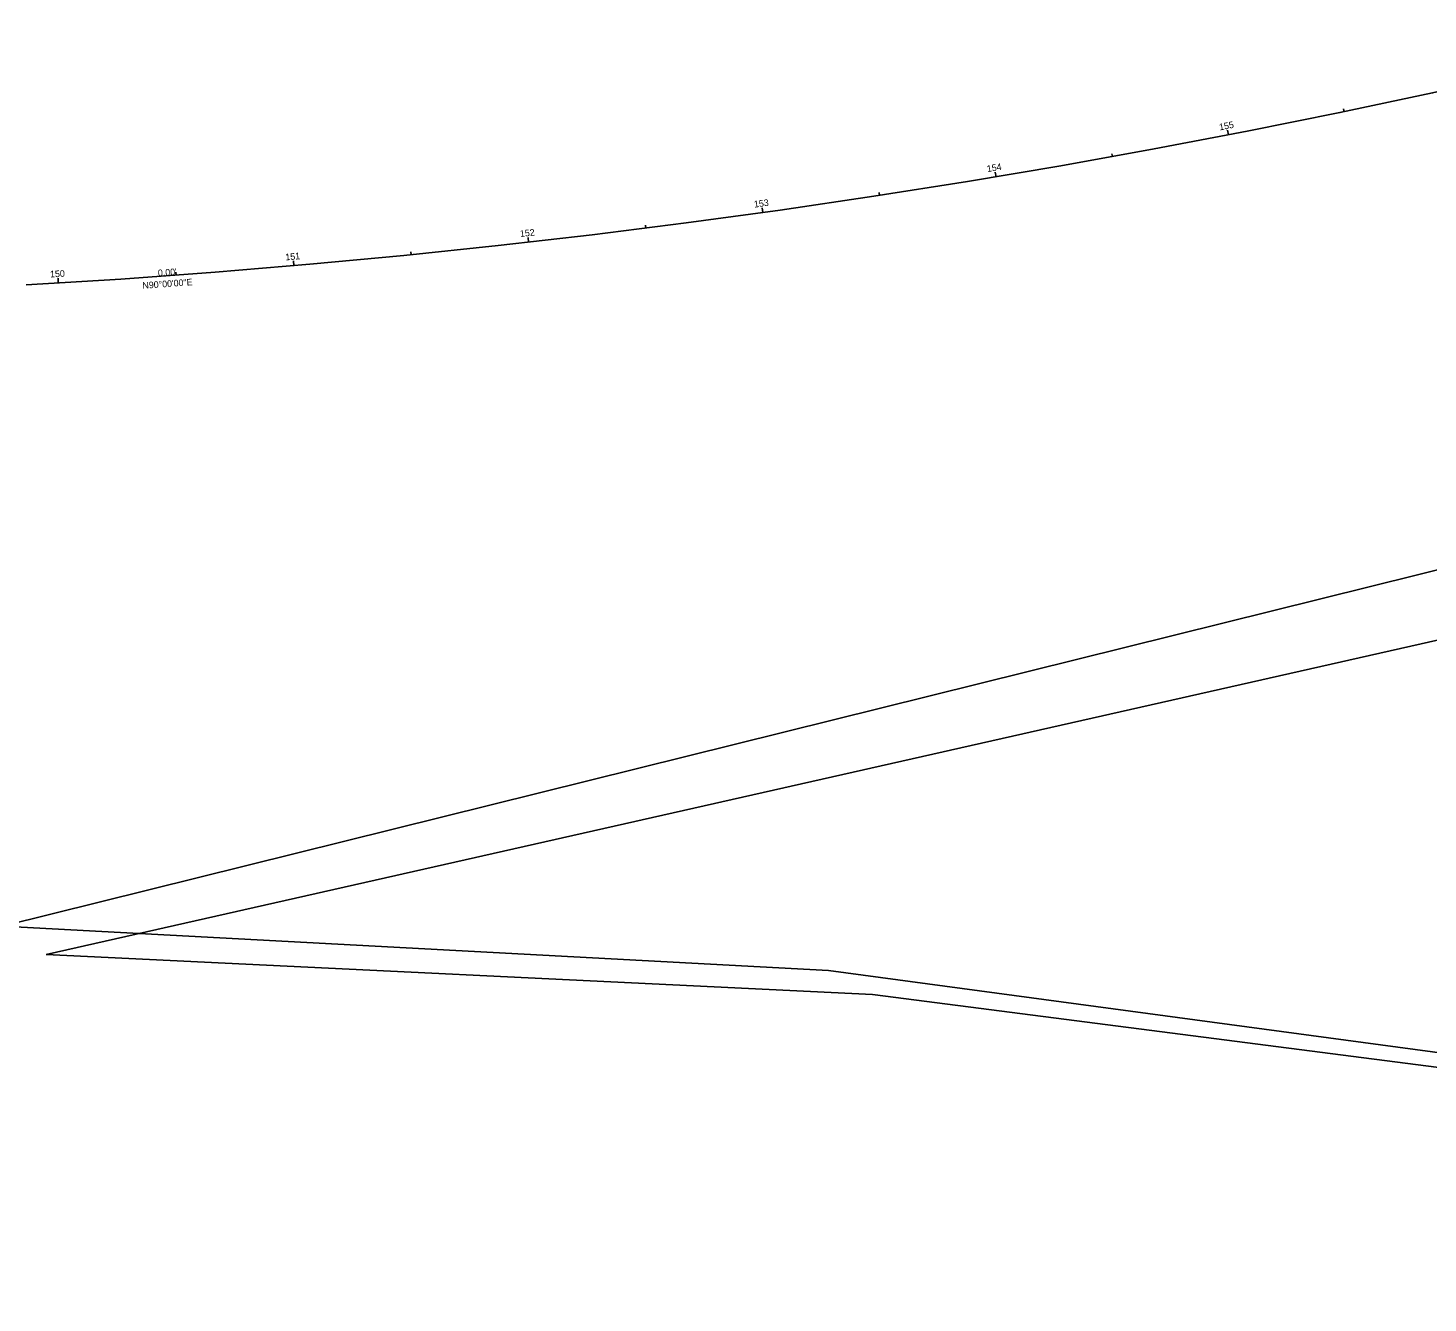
# Model space of a CAD drawing. Extents: x 2272920 to 2277360, y 743591 to 745058.
# Drawn here: x 2275017 to 2275610, y 743599 to 744139 of the extents above; entities that cross this region are included whole.
import ezdxf

# ---------------------------------------------------------------- set-up
doc = ezdxf.new("R2010")
doc.units = 0
for name, color, linetype in [('GE_X_Alignment', 7, 'Continuous'), ('GE_X_Alignment_100_Bearings', 7, 'Continuous'), ('GE_X_Alignment_100_Distances', 7, 'Continuous'), ('GE_X_Alignment_100_Stations', 7, 'Continuous'), ('SC_Scratch1', 7, 'Continuous'), ('SC_Scratch2', 7, 'Continuous')]:
    doc.layers.add(name, color=color, linetype=linetype)

msp = doc.modelspace()

# ---------------------------------------------------------------- linework, layer by layer
at = {"layer": 'GE_X_Alignment'}
msp.add_lwpolyline([(2275015.98, 744030.43), (2275056.03, 744032.92), (2275096.06, 744035.84), (2275136.05, 744039.18), (2275176, 744042.93), (2275215.91, 744047.11), (2275255.78, 744051.7), (2275295.6, 744056.72), (2275335.36, 744062.15), (2275375.06, 744068), (2275414.7, 744074.27), (2275454.27, 744080.95), (2275493.77, 744088.05), (2275533.19, 744095.56), (2275572.53, 744103.48), (2275611.78, 744111.82), (2275650.95, 744120.57), (2275690.02, 744129.73), (2275728.99, 744139.31)], dxfattribs=at)
at = {"layer": 'GE_X_Alignment_100_Stations'}
for p, q in [((2275574.27, 744103.85), (2275574.02, 744105.03)), ((2275525.24, 744094.04), (2275524.86, 744096.01)), ((2275476.09, 744084.87), (2275475.88, 744086.05)), ((2275426.83, 744076.31), (2275426.49, 744078.29)), ((2275377.46, 744068.38), (2275377.27, 744069.56)), ((2275327.99, 744061.14), (2275327.72, 744063.13)), ((2275228.78, 744048.59), (2275228.55, 744050.58)), ((2275278.42, 744054.56), (2275278.27, 744055.75)), ((2275179.07, 744043.25), (2275178.94, 744044.45)), ((2275129.28, 744038.61), (2275129.12, 744040.61)), ((2275029.56, 744031.27), (2275029.43, 744033.27)), ((2275079.44, 744034.63), (2275079.36, 744035.83))]:
    msp.add_line(p, q, dxfattribs=at)
at = {"layer": 'SC_Scratch1'}
for p, q in [((2275024.43, 743746.78), (2275727.62, 743905.62)), ((2275374.48, 743729.8), (2275024.43, 743746.78)), ((2275721.86, 743684.94), (2275374.48, 743729.8))]:
    msp.add_line(p, q, dxfattribs=at)
msp.add_lwpolyline([(2275015.98, 744030.43), (2275056.03, 744032.92), (2275096.06, 744035.84), (2275136.05, 744039.18), (2275176, 744042.93), (2275215.91, 744047.11), (2275255.78, 744051.7), (2275295.6, 744056.72), (2275335.36, 744062.15), (2275375.06, 744068), (2275414.7, 744074.27), (2275454.27, 744080.95), (2275493.77, 744088.05), (2275533.19, 744095.56), (2275572.53, 744103.48), (2275611.78, 744111.82), (2275650.95, 744120.57), (2275690.02, 744129.73), (2275728.99, 744139.31)], dxfattribs=at)
at = {"layer": 'SC_Scratch2'}
msp.add_lwpolyline([(2276160.8, 743900.74), (2276117.26, 743893.3), (2276072.07, 743874.65), (2276031.68, 743846.31), (2275750.53, 743599.11), (2275702.95, 743693.25), (2275355.81, 743739.96), (2275005.85, 743758.81), (2276060.88, 744020.73), (2276162.21, 744051.36)], dxfattribs=at)

# ---------------------------------------------------------------- texts
at = {"layer": 'GE_X_Alignment_100_Bearings'}
msp.add_text('N90°00\'00"E', height=2.8, rotation=4.16747, dxfattribs=at).set_placement((2275065.31, 744028.79))
at = {"layer": 'GE_X_Alignment_100_Distances'}
msp.add_text("0.00'", height=2.8, rotation=4.16747, dxfattribs=at).set_placement((2275071.85, 744034.11))
at = {"layer": 'GE_X_Alignment_100_Stations'}
for s, rotation, p in [('155', 10.78902, (2275521.62, 744095.9)), ('154', 9.5851, (2275423.18, 744078.23)), ('153', 7.77922, (2275324.48, 744063.19)), ('152', 6.5753, (2275225.3, 744050.71)), ('151', 4.76943, (2275125.86, 744040.84)), ('150', 3.56551, (2275026.14, 744033.57))]:
    msp.add_text(s, height=2.8, rotation=rotation, dxfattribs=at).set_placement(p)

doc.saveas('drawing.dxf')
